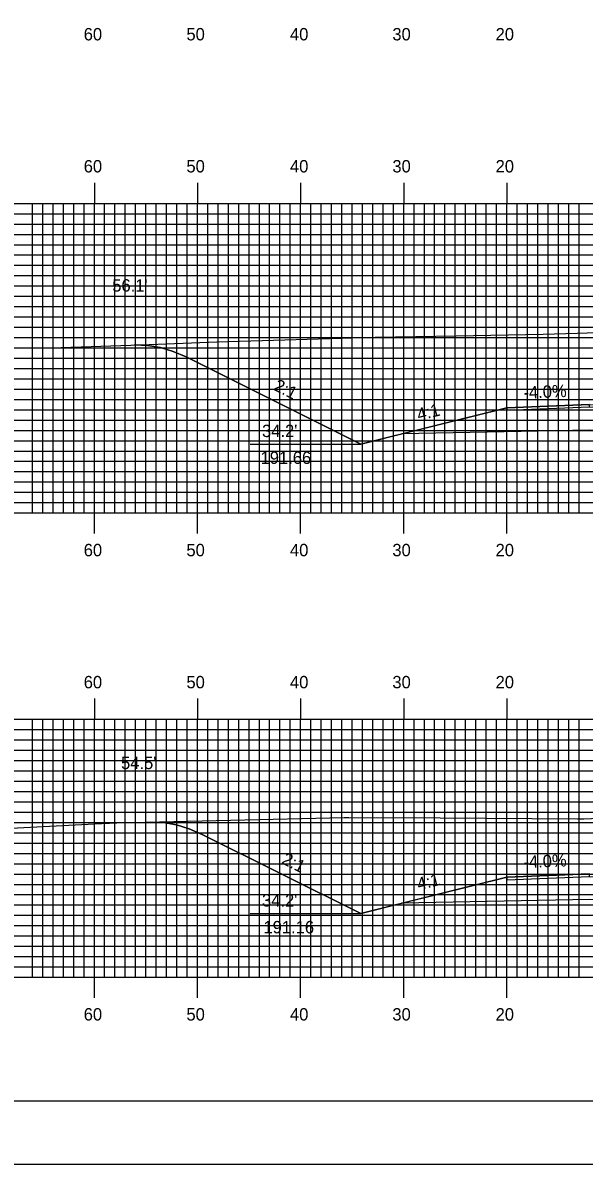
# Model space of a CAD drawing. Extents: x 1799568 to 1799912, y 442591 to 442811.
# Drawn here: x 1799667.1 to 1799721.5, y 442590.5 to 442701.2 of the extents above; entities that cross this region are included whole.
import ezdxf

# ---------------------------------------------------------------- set-up
doc = ezdxf.new("R2010")
doc.units = 0
for name, color, linetype in [('ANNOTATION', 7, 'Continuous'), ('BORDER', 7, 'Continuous'), ('D_Roadway_Centerline', 7, 'Continuous'), ('D_Roadway_Edge_Shoulder', 7, 'Continuous'), ('D_Roadway_SlopeLines', 7, 'Continuous'), ('D_Roadway_SubGrade', 7, 'Continuous'), ('D_Text_Standard', 7, 'Continuous'), ('H_V ANNOTATION', 7, 'Continuous'), ('MAJOR', 7, 'Continuous'), ('MINOR', 7, 'Continuous'), ('PDRAIN', 7, 'Continuous'), ('PLOT BOUNDARY', 7, 'Continuous'), ('S_Roadway_Centerline', 7, 'Continuous')]:
    doc.layers.add(name, color=color, linetype=linetype)

msp = doc.modelspace()

# ---------------------------------------------------------------- linework, layer by layer
at = {"layer": 'BORDER'}
msp.add_lwpolyline([(1799584.41, 442596.67), (1799904.41, 442596.67), (1799904.41, 442806.67), (1799584.41, 442806.67)], close=True, dxfattribs=at)
at = {"layer": 'D_Roadway_Centerline'}
for points in [[(1799677.91, 442669.95), (1799679.16, 442669.91), (1799680.41, 442669.7), (1799681.66, 442669.33), (1799682.91, 442668.79), (1799699.84, 442660.33), (1799703.84, 442661.33), (1799714.01, 442663.87), (1799722.01, 442664.19), (1799734.01, 442663.95), (1799746.01, 442663.71), (1799754.01, 442663.39), (1799764.18, 442660.85), (1799768.18, 442659.85), (1799790.9, 442671.2), (1799792.15, 442671.75), (1799793.4, 442672.14), (1799794.65, 442672.38), (1799795.9, 442672.47)], [(1799679.47, 442623.7), (1799680.72, 442623.65), (1799681.97, 442623.43), (1799683.22, 442623.05), (1799684.47, 442622.51), (1799699.84, 442614.83), (1799703.84, 442615.83), (1799714.01, 442618.37), (1799722.01, 442618.69), (1799734.01, 442618.45), (1799746.01, 442618.21), (1799754.01, 442617.89), (1799764.18, 442615.35), (1799768.18, 442614.35), (1799787.19, 442623.85), (1799788.44, 442624.4), (1799789.69, 442624.8), (1799790.94, 442625.05), (1799792.19, 442625.15)]]:
    msp.add_lwpolyline(points, dxfattribs=at)
at = {"layer": 'D_Roadway_Edge_Shoulder'}
for points in [[(1799722.01, 442664.19), (1799714.01, 442663.87), (1799714.01, 442663.62), (1799722.01, 442663.94)], [(1799722.01, 442618.69), (1799714.01, 442618.37), (1799714.01, 442618.12), (1799722.01, 442618.44)]]:
    msp.add_lwpolyline(points, close=True, dxfattribs=at)
at = {"layer": 'D_Roadway_SlopeLines'}
for points in [[(1799699.84, 442660.33), (1799682.91, 442668.79), (1799681.66, 442669.33), (1799680.41, 442669.7), (1799679.16, 442669.91), (1799677.91, 442669.95)], [(1799714.01, 442663.87), (1799699.84, 442660.33)], [(1799699.84, 442614.83), (1799684.47, 442622.51), (1799683.22, 442623.05), (1799681.97, 442623.43), (1799680.72, 442623.65), (1799679.47, 442623.7)], [(1799714.01, 442618.37), (1799699.84, 442614.83)]]:
    msp.add_lwpolyline(points, dxfattribs=at)
at = {"layer": 'D_Roadway_SubGrade'}
for points in [[(1799722.01, 442661.69), (1799703.84, 442661.33), (1799714.01, 442663.87), (1799714.01, 442663.62), (1799722.01, 442663.94), (1799734.01, 442663.7), (1799746.01, 442663.46), (1799754.01, 442663.14), (1799754.01, 442663.39), (1799764.18, 442660.85), (1799746.01, 442661.21), (1799734.01, 442661.45)], [(1799722.01, 442616.19), (1799703.84, 442615.83), (1799714.01, 442618.37), (1799714.01, 442618.12), (1799722.01, 442618.44), (1799734.01, 442618.2), (1799746.01, 442617.96), (1799754.01, 442617.64), (1799754.01, 442617.89), (1799764.18, 442615.35), (1799746.01, 442615.71), (1799734.01, 442615.95)]]:
    msp.add_lwpolyline(points, close=True, dxfattribs=at)
at = {"layer": 'MAJOR'}
for p, q in [((1799674.01, 442685.67), (1799674.01, 442683.67)), ((1799684.01, 442685.67), (1799684.01, 442683.67)), ((1799694.01, 442685.67), (1799694.01, 442683.67)), ((1799704.01, 442685.67), (1799704.01, 442683.67)), ((1799714.01, 442685.67), (1799714.01, 442683.67)), ((1799594.01, 442683.67), (1799874.01, 442683.67)), ((1799594.01, 442683.67), (1799874.01, 442683.67)), ((1799674.01, 442653.67), (1799674.01, 442683.67)), ((1799684.01, 442653.67), (1799684.01, 442683.67)), ((1799694.01, 442653.67), (1799694.01, 442683.67)), ((1799704.01, 442653.67), (1799704.01, 442683.67)), ((1799714.01, 442653.67), (1799714.01, 442683.67)), ((1799594.01, 442678.67), (1799874.01, 442678.67)), ((1799594.01, 442673.67), (1799874.01, 442673.67)), ((1799594.01, 442668.67), (1799874.01, 442668.67)), ((1799594.01, 442663.67), (1799874.01, 442663.67)), ((1799594.01, 442658.67), (1799874.01, 442658.67)), ((1799594.01, 442653.67), (1799874.01, 442653.67)), ((1799594.01, 442653.67), (1799874.01, 442653.67)), ((1799674.01, 442651.66), (1799674.01, 442653.67)), ((1799684.01, 442651.66), (1799684.01, 442653.67)), ((1799694.01, 442651.66), (1799694.01, 442653.67)), ((1799704.01, 442651.66), (1799704.01, 442653.67)), ((1799714.01, 442651.66), (1799714.01, 442653.67)), ((1799674.01, 442635.67), (1799674.01, 442633.67)), ((1799684.01, 442635.67), (1799684.01, 442633.67)), ((1799694.01, 442635.67), (1799694.01, 442633.67)), ((1799704.01, 442635.67), (1799704.01, 442633.67)), ((1799714.01, 442635.67), (1799714.01, 442633.67)), ((1799594.01, 442633.67), (1799874.01, 442633.67)), ((1799594.01, 442633.67), (1799874.01, 442633.67)), ((1799674.01, 442608.67), (1799674.01, 442633.67)), ((1799684.01, 442608.67), (1799684.01, 442633.67)), ((1799694.01, 442608.67), (1799694.01, 442633.67)), ((1799704.01, 442608.67), (1799704.01, 442633.67)), ((1799714.01, 442608.67), (1799714.01, 442633.67)), ((1799594.01, 442628.67), (1799874.01, 442628.67)), ((1799594.01, 442623.67), (1799874.01, 442623.67)), ((1799594.01, 442618.67), (1799874.01, 442618.67)), ((1799594.01, 442613.67), (1799874.01, 442613.67)), ((1799594.01, 442608.67), (1799874.01, 442608.67)), ((1799594.01, 442608.67), (1799874.01, 442608.67)), ((1799674.01, 442606.66), (1799674.01, 442608.67)), ((1799684.01, 442606.66), (1799684.01, 442608.67)), ((1799694.01, 442606.66), (1799694.01, 442608.67)), ((1799704.01, 442606.66), (1799704.01, 442608.67)), ((1799714.01, 442606.66), (1799714.01, 442608.67))]:
    msp.add_line(p, q, dxfattribs=at)
at = {"layer": 'MINOR'}
for p, q in [((1799668.01, 442653.67), (1799668.01, 442683.67)), ((1799669.01, 442653.67), (1799669.01, 442683.67)), ((1799670.01, 442653.67), (1799670.01, 442683.67)), ((1799671.01, 442653.67), (1799671.01, 442683.67)), ((1799672.01, 442653.67), (1799672.01, 442683.67)), ((1799673.01, 442653.67), (1799673.01, 442683.67)), ((1799675.01, 442653.67), (1799675.01, 442683.67)), ((1799676.01, 442653.67), (1799676.01, 442683.67)), ((1799677.01, 442653.67), (1799677.01, 442683.67)), ((1799678.01, 442653.67), (1799678.01, 442683.67)), ((1799679.01, 442653.67), (1799679.01, 442683.67)), ((1799680.01, 442653.67), (1799680.01, 442683.67)), ((1799681.01, 442653.67), (1799681.01, 442683.67)), ((1799682.01, 442653.67), (1799682.01, 442683.67)), ((1799683.01, 442653.67), (1799683.01, 442683.67)), ((1799685.01, 442653.67), (1799685.01, 442683.67)), ((1799686.01, 442653.67), (1799686.01, 442683.67)), ((1799687.01, 442653.67), (1799687.01, 442683.67)), ((1799688.01, 442653.67), (1799688.01, 442683.67)), ((1799689.01, 442653.67), (1799689.01, 442683.67)), ((1799690.01, 442653.67), (1799690.01, 442683.67)), ((1799691.01, 442653.67), (1799691.01, 442683.67)), ((1799692.01, 442653.67), (1799692.01, 442683.67)), ((1799693.01, 442653.67), (1799693.01, 442683.67)), ((1799695.01, 442653.67), (1799695.01, 442683.67)), ((1799696.01, 442653.67), (1799696.01, 442683.67)), ((1799697.01, 442653.67), (1799697.01, 442683.67)), ((1799698.01, 442653.67), (1799698.01, 442683.67)), ((1799699.01, 442653.67), (1799699.01, 442683.67)), ((1799700.01, 442653.67), (1799700.01, 442683.67)), ((1799701.01, 442653.67), (1799701.01, 442683.67)), ((1799702.01, 442653.67), (1799702.01, 442683.67)), ((1799703.01, 442653.67), (1799703.01, 442683.67)), ((1799705.01, 442653.67), (1799705.01, 442683.67)), ((1799706.01, 442653.67), (1799706.01, 442683.67)), ((1799707.01, 442653.67), (1799707.01, 442683.67)), ((1799708.01, 442653.67), (1799708.01, 442683.67)), ((1799709.01, 442653.67), (1799709.01, 442683.67)), ((1799710.01, 442653.67), (1799710.01, 442683.67)), ((1799711.01, 442653.67), (1799711.01, 442683.67)), ((1799712.01, 442653.67), (1799712.01, 442683.67)), ((1799713.01, 442653.67), (1799713.01, 442683.67)), ((1799715.01, 442653.67), (1799715.01, 442683.67)), ((1799716.01, 442653.67), (1799716.01, 442683.67)), ((1799717.01, 442653.67), (1799717.01, 442683.67)), ((1799718.01, 442653.67), (1799718.01, 442683.67)), ((1799719.01, 442653.67), (1799719.01, 442683.67)), ((1799720.01, 442653.67), (1799720.01, 442683.67)), ((1799721.01, 442653.67), (1799721.01, 442683.67)), ((1799594.01, 442682.67), (1799874.01, 442682.67)), ((1799594.01, 442681.67), (1799874.01, 442681.67)), ((1799594.01, 442680.67), (1799874.01, 442680.67)), ((1799594.01, 442679.67), (1799874.01, 442679.67)), ((1799594.01, 442677.67), (1799874.01, 442677.67)), ((1799594.01, 442676.67), (1799874.01, 442676.67)), ((1799594.01, 442675.67), (1799874.01, 442675.67)), ((1799594.01, 442674.67), (1799874.01, 442674.67)), ((1799594.01, 442672.67), (1799874.01, 442672.67)), ((1799594.01, 442671.67), (1799874.01, 442671.67)), ((1799594.01, 442670.67), (1799874.01, 442670.67)), ((1799594.01, 442669.67), (1799874.01, 442669.67)), ((1799594.01, 442667.67), (1799874.01, 442667.67)), ((1799594.01, 442666.67), (1799874.01, 442666.67)), ((1799594.01, 442665.67), (1799874.01, 442665.67)), ((1799594.01, 442664.67), (1799874.01, 442664.67)), ((1799594.01, 442662.67), (1799874.01, 442662.67)), ((1799594.01, 442661.67), (1799874.01, 442661.67)), ((1799594.01, 442660.67), (1799874.01, 442660.67)), ((1799594.01, 442659.67), (1799874.01, 442659.67)), ((1799594.01, 442657.67), (1799874.01, 442657.67)), ((1799594.01, 442656.67), (1799874.01, 442656.67)), ((1799594.01, 442655.67), (1799874.01, 442655.67)), ((1799594.01, 442654.67), (1799874.01, 442654.67)), ((1799668.01, 442608.67), (1799668.01, 442633.67)), ((1799669.01, 442608.67), (1799669.01, 442633.67)), ((1799670.01, 442608.67), (1799670.01, 442633.67)), ((1799671.01, 442608.67), (1799671.01, 442633.67)), ((1799672.01, 442608.67), (1799672.01, 442633.67)), ((1799673.01, 442608.67), (1799673.01, 442633.67)), ((1799675.01, 442608.67), (1799675.01, 442633.67)), ((1799676.01, 442608.67), (1799676.01, 442633.67)), ((1799677.01, 442608.67), (1799677.01, 442633.67)), ((1799678.01, 442608.67), (1799678.01, 442633.67)), ((1799679.01, 442608.67), (1799679.01, 442633.67)), ((1799680.01, 442608.67), (1799680.01, 442633.67)), ((1799681.01, 442608.67), (1799681.01, 442633.67)), ((1799682.01, 442608.67), (1799682.01, 442633.67)), ((1799683.01, 442608.67), (1799683.01, 442633.67)), ((1799685.01, 442608.67), (1799685.01, 442633.67)), ((1799686.01, 442608.67), (1799686.01, 442633.67)), ((1799687.01, 442608.67), (1799687.01, 442633.67)), ((1799688.01, 442608.67), (1799688.01, 442633.67)), ((1799689.01, 442608.67), (1799689.01, 442633.67)), ((1799690.01, 442608.67), (1799690.01, 442633.67)), ((1799691.01, 442608.67), (1799691.01, 442633.67)), ((1799692.01, 442608.67), (1799692.01, 442633.67)), ((1799693.01, 442608.67), (1799693.01, 442633.67)), ((1799695.01, 442608.67), (1799695.01, 442633.67)), ((1799696.01, 442608.67), (1799696.01, 442633.67)), ((1799697.01, 442608.67), (1799697.01, 442633.67)), ((1799698.01, 442608.67), (1799698.01, 442633.67)), ((1799699.01, 442608.67), (1799699.01, 442633.67)), ((1799700.01, 442608.67), (1799700.01, 442633.67)), ((1799701.01, 442608.67), (1799701.01, 442633.67)), ((1799702.01, 442608.67), (1799702.01, 442633.67)), ((1799703.01, 442608.67), (1799703.01, 442633.67)), ((1799705.01, 442608.67), (1799705.01, 442633.67)), ((1799706.01, 442608.67), (1799706.01, 442633.67)), ((1799707.01, 442608.67), (1799707.01, 442633.67)), ((1799708.01, 442608.67), (1799708.01, 442633.67)), ((1799709.01, 442608.67), (1799709.01, 442633.67)), ((1799710.01, 442608.67), (1799710.01, 442633.67)), ((1799711.01, 442608.67), (1799711.01, 442633.67)), ((1799712.01, 442608.67), (1799712.01, 442633.67)), ((1799713.01, 442608.67), (1799713.01, 442633.67)), ((1799715.01, 442608.67), (1799715.01, 442633.67)), ((1799716.01, 442608.67), (1799716.01, 442633.67)), ((1799717.01, 442608.67), (1799717.01, 442633.67)), ((1799718.01, 442608.67), (1799718.01, 442633.67)), ((1799719.01, 442608.67), (1799719.01, 442633.67)), ((1799720.01, 442608.67), (1799720.01, 442633.67)), ((1799721.01, 442608.67), (1799721.01, 442633.67)), ((1799594.01, 442632.67), (1799874.01, 442632.67)), ((1799594.01, 442631.67), (1799874.01, 442631.67)), ((1799594.01, 442630.67), (1799874.01, 442630.67)), ((1799594.01, 442629.67), (1799874.01, 442629.67)), ((1799594.01, 442627.67), (1799874.01, 442627.67)), ((1799594.01, 442626.67), (1799874.01, 442626.67)), ((1799594.01, 442625.67), (1799874.01, 442625.67)), ((1799594.01, 442624.67), (1799874.01, 442624.67)), ((1799594.01, 442622.67), (1799874.01, 442622.67)), ((1799594.01, 442621.67), (1799874.01, 442621.67)), ((1799594.01, 442620.67), (1799874.01, 442620.67)), ((1799594.01, 442619.67), (1799874.01, 442619.67)), ((1799594.01, 442617.67), (1799874.01, 442617.67)), ((1799594.01, 442616.67), (1799874.01, 442616.67)), ((1799594.01, 442615.67), (1799874.01, 442615.67)), ((1799594.01, 442614.67), (1799874.01, 442614.67)), ((1799594.01, 442612.67), (1799874.01, 442612.67)), ((1799594.01, 442611.67), (1799874.01, 442611.67)), ((1799594.01, 442610.67), (1799874.01, 442610.67)), ((1799594.01, 442609.67), (1799874.01, 442609.67))]:
    msp.add_line(p, q, dxfattribs=at)
at = {"layer": 'PDRAIN'}
for p, q in [((1799689.11, 442660.33), (1799699.84, 442660.33)), ((1799689.11, 442614.83), (1799699.84, 442614.83))]:
    msp.add_line(p, q, dxfattribs=at)
at = {"layer": 'PLOT BOUNDARY'}
msp.add_lwpolyline([(1799568.22, 442590.55), (1799908.22, 442590.55), (1799908.22, 442810.55), (1799568.22, 442810.55)], close=True, dxfattribs=at)
at = {"layer": 'S_Roadway_Centerline'}
for points in [[(1799663.02, 442669.64), (1799669.83, 442669.67), (1799678.53, 442669.97), (1799685.88, 442670.24), (1799701.25, 442670.72), (1799709.09, 442670.84), (1799717.53, 442671.01), (1799720.83, 442671.08), (1799723.76, 442671.18), (1799741.01, 442671.65), (1799743.94, 442671.73), (1799747.42, 442671.95), (1799756.48, 442672.48), (1799764.88, 442672.12), (1799770.81, 442672.2), (1799779.87, 442672.79), (1799787.51, 442672.56), (1799793.12, 442672.45), (1799811.05, 442672.58)], [(1799663.42, 442623), (1799674.03, 442623.55), (1799676.18, 442623.63), (1799698.23, 442624.14), (1799698.46, 442624.15), (1799698.68, 442624.15), (1799707.54, 442624.1), (1799720.87, 442624.03), (1799721.49, 442624.03), (1799732.71, 442624.5), (1799744.31, 442624.41), (1799756.34, 442624.55), (1799768.01, 442624.58), (1799779.63, 442625.06), (1799790.42, 442625.1), (1799791.61, 442625.13), (1799813.9, 442626.06)]]:
    msp.add_lwpolyline(points, dxfattribs=at)

# ---------------------------------------------------------------- texts
at = {"layer": 'ANNOTATION'}
for s, rotation, p in [('2:1', 333.4349, (1799691.31, 442665.63)), ('-4.0%', 2.2906, (1799715.64, 442664.74)), ('4:1', 14.0362, (1799705.46, 442662.59)), ('2:1', 333.4349, (1799692.09, 442619.74)), ('-4.0%', 2.2906, (1799715.64, 442619.24)), ('4:1', 14.0362, (1799705.46, 442617.09))]:
    msp.add_text(s, height=1.2, rotation=rotation, dxfattribs=at).set_placement(p)
for s, p in [("34.2'", (1799690.27, 442661.02)), ('191.66', (1799690.13, 442658.42)), ("34.2'", (1799690.27, 442615.52)), ('191.16', (1799690.41, 442612.92))]:
    msp.add_text(s, height=1.2, dxfattribs=at).set_placement(p)
at = {"layer": 'D_Text_Standard'}
for s, p in [("56.1'", (1799675.75, 442675.12)), ("54.5'", (1799676.6, 442628.84))]:
    msp.add_text(s, height=1.2, dxfattribs=at).set_placement(p)
at = {"layer": 'H_V ANNOTATION'}
for s, p in [('60', (1799672.98, 442699.47)), ('50', (1799682.94, 442699.47)), ('40', (1799692.98, 442699.47)), ('30', (1799702.91, 442699.47)), ('20', (1799712.92, 442699.47)), ('60', (1799672.98, 442686.67)), ('50', (1799682.94, 442686.67)), ('40', (1799692.98, 442686.67)), ('30', (1799702.91, 442686.67)), ('20', (1799712.92, 442686.67)), ('60', (1799672.98, 442649.47)), ('50', (1799682.94, 442649.47)), ('40', (1799692.98, 442649.47)), ('30', (1799702.91, 442649.47)), ('20', (1799712.92, 442649.47)), ('60', (1799672.98, 442636.67)), ('50', (1799682.94, 442636.67)), ('40', (1799692.98, 442636.67)), ('30', (1799702.91, 442636.67)), ('20', (1799712.92, 442636.67)), ('60', (1799672.98, 442604.47)), ('50', (1799682.94, 442604.47)), ('40', (1799692.98, 442604.47)), ('30', (1799702.91, 442604.47)), ('20', (1799712.92, 442604.47))]:
    msp.add_text(s, height=1.2, dxfattribs=at).set_placement(p)

doc.saveas('drawing.dxf')
